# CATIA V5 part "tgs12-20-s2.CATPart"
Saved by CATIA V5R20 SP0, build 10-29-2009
Part number: TGS12-20-S2
Revision: 1
Definition: design
Nomenclature: TGS12-20-S2
Source: made
Description: NOT SPECIFIED
Bounding box of the stored display mesh (mm): x -22 to 0.8, y 0 to 12, z -5 to 5
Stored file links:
  C:\Users\Raffaele\Desktop\3D X SITO CF\I-MOLD\TGS-S2\tgs12-s2.step\tgs12-20-s2.CATPart
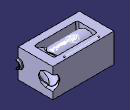
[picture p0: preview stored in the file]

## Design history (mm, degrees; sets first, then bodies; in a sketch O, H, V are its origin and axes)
Set1
  Line1 "LINE #3946": stored without definition
  DatumCurve1 "COMPOSITE_CURVE #4001"
  DatumCurve2 "COMPOSITE_CURVE #4050"
  DatumCurve3 "COMPOSITE_CURVE #4129"
  DatumCurve4 "COMPOSITE_CURVE #4172"
  DatumCurve5 "COMPOSITE_CURVE #4401"
  DatumCurve6 "COMPOSITE_CURVE #4542"
  DatumCurve7 "COMPOSITE_CURVE #4569"
  DatumCurve8 "COMPOSITE_CURVE #4627"
  DatumCurve9 "COMPOSITE_CURVE #4684"
  DatumCurve10 "COMPOSITE_CURVE #4713"
  DatumSurface1 "OPEN_SHELL #3936"
Body1 "MANIFOLD_SOLID_BREP #3937" (main body)
  Solid1: solid without history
